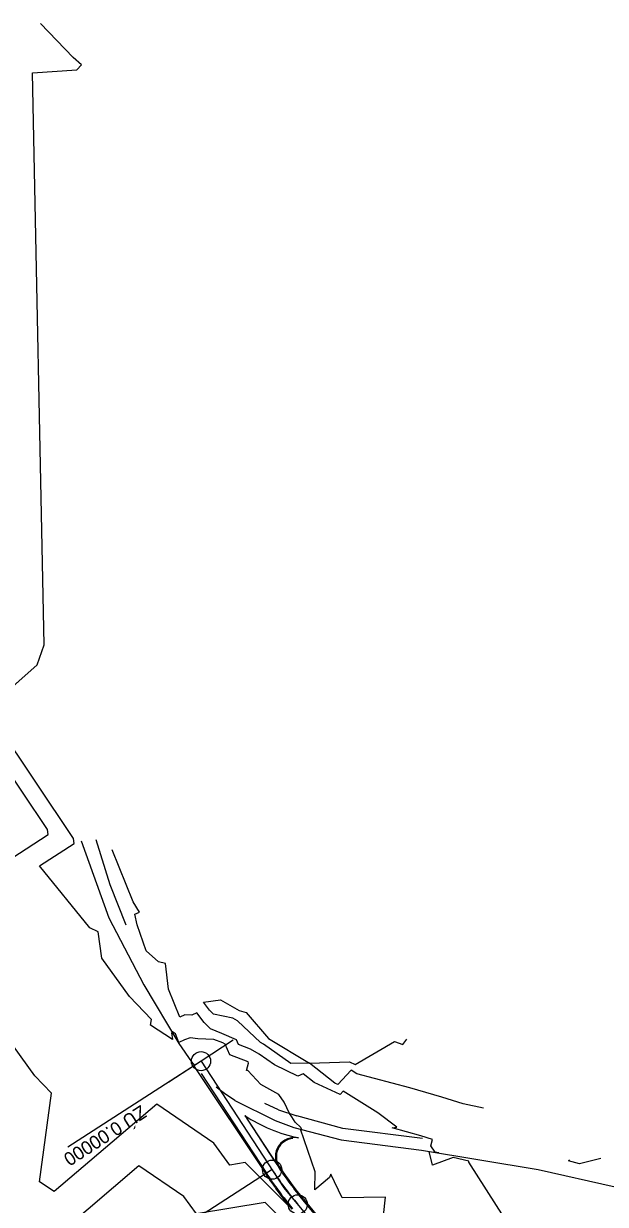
# Model space of a CAD drawing. Extents: x -549394 to -546608, y -1037055 to -1033629.
# Drawn here: x -547148.3 to -546996.5, y -1035794.7 to -1035486.4 of the extents above; entities that cross this region are included whole.
import ezdxf

# ---------------------------------------------------------------- set-up
doc = ezdxf.new("R2010")
doc.units = 0
for name, color, linetype in [('hlavni_vrst', 7, 'Continuous'), ('hrana_L', 7, 'Continuous'), ('norm_vrst', 7, 'Continuous'), ('POLYGONY_SITUACE_PO', 7, 'Continuous'), ('x_navrh_C31', 7, 'Continuous'), ('x_osa_C31', 7, 'Continuous'), ('x_popis_oblouky_C31', 7, 'Continuous'), ('x_popis_pricne_rezy_C31', 7, 'Continuous'), ('x_rozsireni_srafa_C31', 7, 'Continuous')]:
    doc.layers.add(name, color=color, linetype=linetype)

msp = doc.modelspace()

# ---------------------------------------------------------------- linework, layer by layer
at = {"layer": 'hlavni_vrst'}
for p, q in [((-547119.76, -1035715.7), (-547125.23, -1035702.15)), ((-547118.11, -1035718.38), (-547119.76, -1035715.7)), ((-547119.32, -1035718.91), (-547118.11, -1035718.38)), ((-547118.72, -1035721.68), (-547119.32, -1035718.91)), ((-547116.35, -1035728.46), (-547118.72, -1035721.68)), ((-547113.14, -1035731.35), (-547116.35, -1035728.46)), ((-547111.32, -1035731.79), (-547113.14, -1035731.35)), ((-547110.54, -1035738.54), (-547111.32, -1035731.79)), ((-547107.57, -1035745.83), (-547110.54, -1035738.54)), ((-547106.28, -1035745.18), (-547107.57, -1035745.83)), ((-547104.38, -1035745.28), (-547106.28, -1035745.18)), ((-547103.1, -1035744.71), (-547104.38, -1035745.28)), ((-547101.24, -1035747.24), (-547103.1, -1035744.71)), ((-547099.56, -1035748.9), (-547101.24, -1035747.24)), ((-547096.55, -1035750.05), (-547099.56, -1035748.9)), ((-547092.78, -1035751.76), (-547096.55, -1035750.05)), ((-547092.25, -1035752.99), (-547092.78, -1035751.76)), ((-547089.09, -1035754.2), (-547092.25, -1035752.99)), ((-547086.83, -1035755.45), (-547089.09, -1035754.2)), ((-547082.83, -1035758.29), (-547086.83, -1035755.45)), ((-547076.73, -1035761.22), (-547082.83, -1035758.29)), ((-547075.38, -1035760.61), (-547076.73, -1035761.22)), ((-547072.5, -1035762.9), (-547075.38, -1035760.61)), ((-547065.74, -1035766.01), (-547072.5, -1035762.9)), ((-547064.9, -1035765.1), (-547065.74, -1035766.01)), ((-547055.9, -1035770.76), (-547064.9, -1035765.1)), ((-547050.97, -1035774.54), (-547055.9, -1035770.76)), ((-547052.14, -1035774.74), (-547050.97, -1035774.54)), ((-547044.71, -1035776.82), (-547052.14, -1035774.74)), ((-547041.66, -1035777.75), (-547044.71, -1035776.82)), ((-547042.1, -1035779.39), (-547041.66, -1035777.75)), ((-547041.65, -1035784.48), (-547042.49, -1035780.85)), ((-547042.49, -1035780.85), (-547039.99, -1035781.26)), ((-547040.91, -1035781.03), (-547042.1, -1035779.39)), ((-547039.99, -1035781.26), (-547040.91, -1035781.03)), ((-547036.28, -1035782.48), (-547041.65, -1035784.48)), ((-547032.12, -1035783.41), (-547036.28, -1035782.48)), ((-547032.16, -1035783.69), (-547032.12, -1035783.41)), ((-547022.93, -1035798.11), (-547032.16, -1035783.69))]:
    msp.add_line(p, q, dxfattribs=at)
at = {"layer": 'hrana_L'}
for p, q in [((-547133.31, -1035699.8), (-547126.03, -1035719.9)), ((-547125.75, -1035711.25), (-547129.4, -1035699.51)), ((-547121.54, -1035721.79), (-547125.75, -1035711.25)), ((-547126.03, -1035719.9), (-547116.97, -1035737.34)), ((-547116.97, -1035737.34), (-547107.79, -1035752.71)), ((-547107.79, -1035752.71), (-547104.47, -1035757.48)), ((-547104.47, -1035757.48), (-547103.62, -1035758.54)), ((-547095.87, -1035765.77), (-547098.09, -1035764.1)), ((-547093.16, -1035767.56), (-547095.87, -1035765.77)), ((-547093.16, -1035767.56), (-547082.65, -1035772.78)), ((-547081.81, -1035770.01), (-547085.39, -1035768.38)), ((-547081.81, -1035770.01), (-547076.99, -1035771.58)), ((-547065.04, -1035774.86), (-547076.99, -1035771.58)), ((-547082.65, -1035772.78), (-547077.83, -1035774.58)), ((-547077.83, -1035774.58), (-547065.49, -1035777.83)), ((-547044.23, -1035777.49), (-547065.04, -1035774.86)), ((-547065.49, -1035777.83), (-547044.51, -1035780.5)), ((-547044.51, -1035780.5), (-547014.03, -1035785.6)), ((-547014.03, -1035785.6), (-546993.98, -1035790.12))]:
    msp.add_line(p, q, dxfattribs=at)
at = {"layer": 'norm_vrst'}
for p, q in [((-547135.36, -1035495.23), (-547143.87, -1035486.4)), ((-547133.21, -1035497.17), (-547135.36, -1035495.23)), ((-547134.4, -1035498.49), (-547133.21, -1035497.17)), ((-547145.95, -1035499.25), (-547134.4, -1035498.49)), ((-547142.94, -1035648.57), (-547145.95, -1035499.25)), ((-547142.07, -1035696.85), (-547242.38, -1035546.99)), ((-547144.77, -1035653.79), (-547142.94, -1035648.57)), ((-547157.83, -1035665.45), (-547144.77, -1035653.79)), ((-547135.28, -1035699.14), (-547157.83, -1035665.45)), ((-547141.94, -1035698.11), (-547142.07, -1035696.85)), ((-547184.42, -1035725.79), (-547141.94, -1035698.11)), ((-547144.18, -1035706.34), (-547135.14, -1035700.46)), ((-547135.14, -1035700.46), (-547135.28, -1035699.14)), ((-547131.02, -1035722.49), (-547144.18, -1035706.34)), ((-547128.86, -1035723.52), (-547131.02, -1035722.49)), ((-547127.92, -1035730.37), (-547128.86, -1035723.52)), ((-547120.68, -1035740.44), (-547127.92, -1035730.37)), ((-547114.98, -1035746.4), (-547120.68, -1035740.44)), ((-547101.36, -1035741.88), (-547096.97, -1035741.25)), ((-547099.84, -1035743.95), (-547101.36, -1035741.88)), ((-547098.79, -1035744.99), (-547099.84, -1035743.95)), ((-547096.97, -1035741.25), (-547092.03, -1035744.04)), ((-547092.03, -1035744.04), (-547090.21, -1035744.59)), ((-547115.18, -1035747.91), (-547114.98, -1035746.4)), ((-547093.75, -1035746.09), (-547098.79, -1035744.99)), ((-547092.47, -1035746.77), (-547093.75, -1035746.09)), ((-547086.48, -1035752.45), (-547092.47, -1035746.77)), ((-547090.21, -1035744.59), (-547084.45, -1035751.36)), ((-547109.47, -1035751.65), (-547115.18, -1035747.91)), ((-547109.33, -1035750.16), (-547109.74, -1035749.92)), ((-547109.74, -1035749.92), (-547109.47, -1035751.65)), ((-547109.72, -1035749.47), (-547109.33, -1035750.16)), ((-547108.72, -1035750.14), (-547109.72, -1035749.47)), ((-547107.78, -1035752.45), (-547108.72, -1035750.14)), ((-547145.41, -1035761.11), (-547150.95, -1035753.4)), ((-547106.32, -1035751.7), (-547107.78, -1035752.45)), ((-547104.82, -1035751.21), (-547106.32, -1035751.7)), ((-547102.85, -1035751.5), (-547104.82, -1035751.21)), ((-547098.7, -1035751.63), (-547102.85, -1035751.5)), ((-547096.32, -1035752.55), (-547098.7, -1035751.63)), ((-547095.69, -1035752.83), (-547096.32, -1035752.55)), ((-547094.49, -1035755.63), (-547095.69, -1035752.83)), ((-547085.76, -1035752.84), (-547086.48, -1035752.45)), ((-547078.6, -1035757.93), (-547085.76, -1035752.84)), ((-547084.45, -1035751.36), (-547073.72, -1035757.81)), ((-547061.85, -1035758.15), (-547051.54, -1035752.15)), ((-547051.54, -1035752.15), (-547049.41, -1035752.95)), ((-547049.41, -1035752.95), (-547048.34, -1035751.56)), ((-547089.7, -1035757.46), (-547094.49, -1035755.63)), ((-547090.19, -1035759.74), (-547089.6, -1035757.81)), ((-547089.6, -1035757.81), (-547089.7, -1035757.46)), ((-547073.72, -1035757.81), (-547078.6, -1035757.93)), ((-547073.72, -1035757.81), (-547063.29, -1035757.51)), ((-547073.72, -1035757.81), (-547073.72, -1035757.81)), ((-547073.72, -1035757.81), (-547073.72, -1035757.81)), ((-547073.72, -1035757.81), (-547073.72, -1035757.81)), ((-547067.1, -1035763.08), (-547073.72, -1035757.81)), ((-547063.29, -1035757.51), (-547061.85, -1035758.15)), ((-547141.05, -1035765.67), (-547145.41, -1035761.11)), ((-547089.83, -1035759.74), (-547090.19, -1035759.74)), ((-547086.44, -1035763.39), (-547089.83, -1035759.74)), ((-547062.85, -1035759.69), (-547066.32, -1035763.43)), ((-547061.39, -1035760.61), (-547062.85, -1035759.69)), ((-547047.55, -1035764.26), (-547061.39, -1035760.61)), ((-547144.14, -1035788.82), (-547141.05, -1035765.67)), ((-547081.68, -1035765.99), (-547086.44, -1035763.39)), ((-547066.32, -1035763.43), (-547067.1, -1035763.08)), ((-547039.2, -1035766.69), (-547047.55, -1035764.26)), ((-547113.56, -1035768.54), (-547140.31, -1035791.32)), ((-547098.64, -1035778.68), (-547113.56, -1035768.54)), ((-547080.36, -1035767.97), (-547081.68, -1035765.99)), ((-547078.92, -1035770.95), (-547080.36, -1035767.97)), ((-547033.59, -1035768.43), (-547039.2, -1035766.69)), ((-547028.36, -1035769.53), (-547033.59, -1035768.43)), ((-547078.3, -1035771.86), (-547078.92, -1035770.95)), ((-547077.45, -1035773.22), (-547078.3, -1035771.86)), ((-547076, -1035774.62), (-547077.45, -1035773.22)), ((-547075.7, -1035775.14), (-547076, -1035774.62)), ((-547076.04, -1035775.07), (-547075.7, -1035775.14)), ((-547072.24, -1035786.23), (-547076.04, -1035775.07)), ((-547094.5, -1035784.45), (-547098.64, -1035778.68)), ((-547090.47, -1035783.78), (-547094.5, -1035784.45)), ((-547079.24, -1035795.04), (-547090.47, -1035783.78)), ((-547006.15, -1035783.3), (-547005.9, -1035783.02)), ((-547003.25, -1035784.08), (-547006.15, -1035783.3)), ((-546997.72, -1035782.74), (-547003.25, -1035784.08)), ((-547118.23, -1035784.65), (-547172, -1035830.44)), ((-547106.48, -1035792.64), (-547118.23, -1035784.65)), ((-547072.34, -1035790.87), (-547072.24, -1035786.23)), ((-547068.17, -1035786.78), (-547068.52, -1035787.69)), ((-547065.22, -1035792.95), (-547068.17, -1035786.78)), ((-547140.31, -1035791.32), (-547144.14, -1035788.82)), ((-547068.52, -1035787.69), (-547072.34, -1035790.87)), ((-547103.21, -1035797.19), (-547106.48, -1035792.64)), ((-547053.89, -1035792.84), (-547065.22, -1035792.95)), ((-547055.88, -1035811.62), (-547053.89, -1035792.84)), ((-547085.31, -1035794.19), (-547103.21, -1035797.19)), ((-547078.18, -1035801.34), (-547085.31, -1035794.19))]:
    msp.add_line(p, q, dxfattribs=at)
at = {"layer": 'POLYGONY_SITUACE_PO'}
for centre in [(-547102.02, -1035757.3), (-547083.48, -1035785.62), (-547076.78, -1035794.69)]:
    msp.add_circle(centre, 2.5, dxfattribs=at)
at = {"layer": 'x_navrh_C31'}
for p, q in [((-547103.94, -1035758.47), (-547085.15, -1035786.72)), ((-547102, -1035760.52), (-547084.94, -1035786.58)), ((-547090.63, -1035771.5), (-547082.02, -1035784.66)), ((-547075.24, -1035793.41), (-547060.84, -1035810.78)), ((-547075.44, -1035793.57), (-547061.03, -1035810.94))]:
    msp.add_line(p, q, dxfattribs=at)
for centre, radius, start, end in [((-547077.63, -1035782.24), 5, 77.9095, 213.2057), ((-547077.63, -1035782.24), 4.75, 95.602, 213.2057), ((-546999.81, -1035730.86), 102, 213.2057, 219.6688), ((-546999.81, -1035730.86), 101.75, 213.2057, 219.6688), ((-546999.81, -1035730.86), 98.25, 213.2057, 219.6688), ((-546999.81, -1035730.86), 98, 213.4227, 219.6688)]:
    msp.add_arc(centre, radius, start, end, dxfattribs=at)
at = {"layer": 'x_osa_C31'}
msp.add_lwpolyline([(-547102.02, -1035757.3), (-547080.39, -1035790.35), (-547080.39, -1035790.35), (-547056.73, -1035818.87), (-547022.58, -1035854.58), (-547022.58, -1035854.58), (-547000.23, -1035880.99)], dxfattribs=at)
msp.add_arc((-546999.81, -1035730.86), 100, 213.2057, 219.6688, dxfattribs=at)
at = {"layer": 'x_popis_oblouky_C31'}
for points in [[(-547102.02, -1035757.3), (-547136.75, -1035779.78)], [(-547083.48, -1035785.62), (-547118.21, -1035808.11)]]:
    msp.add_lwpolyline(points, dxfattribs=at)
at = {"layer": 'x_popis_pricne_rezy_C31'}
msp.add_lwpolyline([(-547093.65, -1035751.82), (-547102.02, -1035757.3), (-547110.38, -1035762.78)], dxfattribs=at)
at = {"layer": 'x_rozsireni_srafa_C31'}
for p, q in [((-547090.63, -1035771.5), (-547082.99, -1035783.17)), ((-547082.99, -1035783.17), (-547082.02, -1035784.66))]:
    msp.add_line(p, q, dxfattribs=at)
msp.add_lwpolyline([(-547090.63, -1035771.5), (-547090.63, -1035771.5)], dxfattribs=at)
for centre, radius, start, end in [((-547067.84, -1035736.52), 41.75, 236.91, 257.9095), ((-547077.63, -1035782.24), 5, 77.9095, 192.4881), ((-547083.48, -1035785.62), 2.5, 67.1758, 78.7787), ((-547083.48, -1035785.62), 2.5, 67.1758, 78.7784), ((-547077.63, -1035782.24), 5, 192.4881, 212.4209), ((-546999.81, -1035730.86), 98.25, 213.2057, 213.3827)]:
    msp.add_arc(centre, radius, start, end, dxfattribs=at)

# ---------------------------------------------------------------- texts
at = {"layer": 'x_popis_oblouky_C31'}
msp.add_text('ZÚ 0.00000', height=3.5, rotation=212.918, dxfattribs=at).set_placement((-547117.71, -1035768.64))

doc.saveas('drawing.dxf')
